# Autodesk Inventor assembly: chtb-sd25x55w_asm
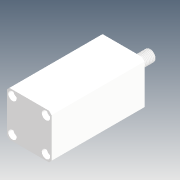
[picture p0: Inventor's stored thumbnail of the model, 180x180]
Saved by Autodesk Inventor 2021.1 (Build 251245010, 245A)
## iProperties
Company: Microsoft
Created: 2018-05
Part Number: chtb-sd25x55w_asm
Description: STEP AP214
Document SubType Name: Assembly
Designer: user
Title: chtb-sd25x55w_asm.STEP
Author: Windows
Revision Number: ÈÎºÎ
Sending System: SolidWorks 2015
Preprocessor: SwSTEP 2.0
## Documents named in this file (4)
- D:\Vault_2016\Projekty\Clamptek\Hydraulic\CHTB\CHTB-25\Inventor\chtb-sd25x55w\chtb-sd25x55w_asm.iam
- D:\Vault_2016\Projekty\Clamptek\Hydraulic\CHTB\CHTB-25\Inventor\chtb-sd25x55w\CHTB-25QG.ipt
- D:\Vault_2016\Projekty\Clamptek\Hydraulic\CHTB\CHTB-25\Inventor\chtb-sd25x55w\CHTB-SD25X55NBT.ipt
- D:\Vault_2016\Projekty\Clamptek\Hydraulic\CHTB\CHTB-25\Inventor\chtb-sd25x55w\CHTB-SD25X55WHSG.ipt
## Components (3 placed, 3 different names)
1. CHTB-25QG_1
2. CHTB-SD25X55NBT_2
3. CHTB-SD25X55WHSG_3
